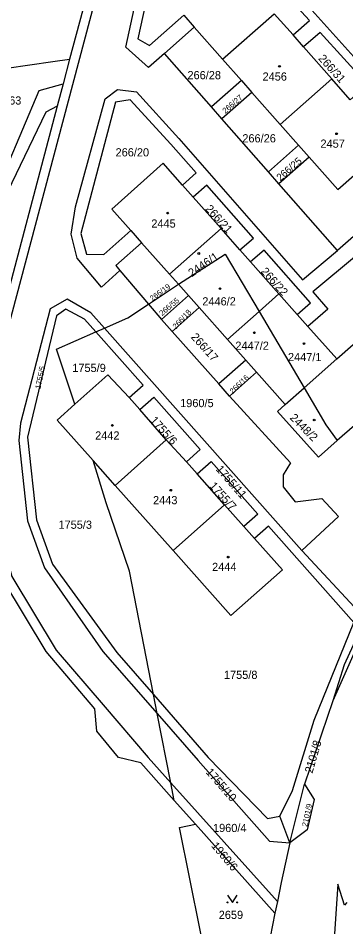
# Model space of a CAD drawing. Extents: x -679220 to -673243, y -1075091 to -1066557.
# Drawn here: x -676420.8 to -676352.8, y -1072199 to -1072010.2 of the extents above; entities that cross this region are included whole.
import ezdxf

# ---------------------------------------------------------------- set-up
doc = ezdxf.new("R2010")
doc.units = 0
for name, color, linetype in [('Hranice parcel', 7, 'Continuous'), ('Parcelní čísla', 7, 'Continuous'), ('Značky budov', 7, 'Continuous'), ('Značky kultur', 7, 'Continuous')]:
    doc.layers.add(name, color=color, linetype=linetype)

msp = doc.modelspace()

# ---------------------------------------------------------------- linework, layer by layer
at = {"layer": 'Hranice parcel'}
for p, q in [((-676405.43, -1072000.99), (-676410.13, -1072018.72)), ((-676386.44, -1072009.61), (-676384.26, -1072012.08)), ((-676378.4, -1072018.73), (-676367.67, -1072009.27)), ((-676363.77, -1072013.69), (-676367.67, -1072009.27)), ((-676384.26, -1072012.08), (-676390.45, -1072017.54)), ((-676384.26, -1072012.08), (-676378.4, -1072018.73)), ((-676361.59, -1072016.16), (-676363.77, -1072013.69)), ((-676355.71, -1072022.83), (-676361.59, -1072016.16)), ((-676410.13, -1072018.72), (-676411.49, -1072023.83)), ((-676380.72, -1072028.63), (-676390.45, -1072017.54)), ((-676378.4, -1072018.73), (-676374.5, -1072023.14)), ((-676374.5, -1072023.14), (-676380.72, -1072028.63)), ((-676374.5, -1072023.14), (-676372.32, -1072025.62)), ((-676366.44, -1072032.28), (-676355.71, -1072022.83)), ((-676351.9, -1072027.15), (-676355.71, -1072022.83)), ((-676411.49, -1072023.83), (-676412.72, -1072028.49)), ((-676372.32, -1072025.62), (-676378.54, -1072031.11)), ((-676372.32, -1072025.62), (-676366.44, -1072032.28)), ((-676412.72, -1072028.49), (-676426.83, -1072081.87)), ((-676378.54, -1072031.11), (-676380.72, -1072028.63)), ((-676368.88, -1072042.12), (-676378.54, -1072031.11)), ((-676366.44, -1072032.28), (-676362.63, -1072036.61)), ((-676362.63, -1072036.61), (-676368.88, -1072042.12)), ((-676362.63, -1072036.61), (-676360.45, -1072039.08)), ((-676360.45, -1072039.08), (-676366.74, -1072044.62)), ((-676333.89, -1072040.27), (-676354.54, -1072058.47)), ((-676366.74, -1072044.62), (-676368.88, -1072042.12)), ((-676384.52, -1072047.4), (-676386.74, -1072044.9)), ((-676354.54, -1072058.47), (-676366.74, -1072044.62)), ((-676378.69, -1072053.93), (-676384.52, -1072047.4)), ((-676397.41, -1072054.36), (-676395.19, -1072056.86)), ((-676389.38, -1072063.42), (-676378.69, -1072053.93)), ((-676374.79, -1072058.37), (-676378.69, -1072053.93)), ((-676395.19, -1072056.86), (-676389.38, -1072063.42)), ((-676372.58, -1072060.87), (-676374.79, -1072058.37)), ((-676366.7, -1072067.49), (-676372.58, -1072060.87)), ((-676399.71, -1072062.61), (-676393.75, -1072069.64)), ((-676387.53, -1072065.5), (-676389.38, -1072063.42)), ((-676393.75, -1072069.64), (-676387.53, -1072065.5)), ((-676387.53, -1072065.5), (-676385.47, -1072067.83)), ((-676354.71, -1072081.03), (-676337.16, -1072065.5)), ((-676385.47, -1072067.83), (-676391.07, -1072072.8)), ((-676383.25, -1072070.33), (-676385.47, -1072067.83)), ((-676370.83, -1072071.15), (-676366.7, -1072067.49)), ((-676362.89, -1072071.81), (-676366.7, -1072067.49)), ((-676393.75, -1072069.64), (-676391.07, -1072072.8)), ((-676388.85, -1072075.3), (-676383.25, -1072070.33)), ((-676383.25, -1072070.33), (-676377.38, -1072076.96)), ((-676377.38, -1072076.96), (-676370.83, -1072071.15)), ((-676370.83, -1072071.15), (-676361.48, -1072087.03)), ((-676360.67, -1072074.31), (-676362.89, -1072071.81)), ((-676391.07, -1072072.8), (-676388.85, -1072075.3)), ((-676404.69, -1072075.41), (-676402.91, -1072074.63)), ((-676361.93, -1072120.84), (-676402.91, -1072074.63)), ((-676379.16, -1072086.23), (-676388.85, -1072075.3)), ((-676360.67, -1072074.31), (-676354.71, -1072081.03)), ((-676377.38, -1072076.96), (-676373.56, -1072081.27)), ((-676373.56, -1072081.27), (-676379.16, -1072086.23)), ((-676373.56, -1072081.27), (-676371.34, -1072083.77)), ((-676361.48, -1072087.03), (-676354.71, -1072081.03)), ((-676371.34, -1072083.77), (-676376.94, -1072088.73)), ((-676365.39, -1072090.49), (-676371.34, -1072083.77)), ((-676376.94, -1072088.73), (-676379.16, -1072086.23)), ((-676365.39, -1072090.49), (-676361.48, -1072087.03)), ((-676397.79, -1072089.04), (-676395.56, -1072091.54)), ((-676342.98, -1072087.79), (-676354.59, -1072098)), ((-676390.07, -1072097.84), (-676395.56, -1072091.54)), ((-676400.65, -1072107.34), (-676390.07, -1072097.84)), ((-676385.89, -1072102.42), (-676390.07, -1072097.84)), ((-676400.65, -1072107.34), (-676405.26, -1072102.16)), ((-676385.89, -1072102.42), (-676383.67, -1072104.92)), ((-676377.99, -1072111.34), (-676383.67, -1072104.92)), ((-676388.66, -1072120.83), (-676400.65, -1072107.34)), ((-676388.66, -1072120.83), (-676377.99, -1072111.34)), ((-676373.97, -1072115.83), (-676377.99, -1072111.34)), ((-676373.97, -1072115.83), (-676371.74, -1072118.34)), ((-676361.93, -1072120.84), (-676350.1, -1072133.56)), ((-676391.97, -1072154.7), (-676392.74, -1072150.74)), ((-676355.54, -1072152.07), (-676361.36, -1072169.41)), ((-676389.15, -1072169.1), (-676391.97, -1072154.7)), ((-676389.15, -1072169.1), (-676367.03, -1072193.77)), ((-676388.43, -1072172.78), (-676389.15, -1072169.1)), ((-676364.45, -1072181.57), (-676361.36, -1072169.41)), ((-676384.02, -1072177.72), (-676388.43, -1072172.78)), ((-676364.45, -1072181.57), (-676366.54, -1072176.02)), ((-676384.02, -1072177.72), (-676367.53, -1072196.21)), ((-676367.03, -1072193.77), (-676367.53, -1072196.21))]:
    msp.add_line(p, q, dxfattribs=at)
for points in [[(-676295.13, -1071902.52), (-676296.41, -1071905.95), (-676304.35, -1071909.5), (-676364.66, -1071925.74), (-676375.64, -1071931.09), (-676382.94, -1071938.2), (-676387.67, -1071944.57), (-676393.17, -1071962.19), (-676409.55, -1072024.04), (-676425.12, -1072082.52), (-676427.14, -1072091.8), (-676426.89, -1072108.9), (-676422.15, -1072126.21), (-676412.96, -1072141.55), (-676403.18, -1072152.89), (-676393.86, -1072163.85), (-676389.15, -1072169.1)], [(-676390.45, -1072017.54), (-676393.75, -1072020.45), (-676398.47, -1072016.2), (-676391.69, -1071984.93), (-676388.01, -1071980.59), (-676383.5, -1071982.16), (-676332.46, -1072039.02)], [(-676375.71, -1072000.14), (-676372.54, -1071997.35), (-676384.98, -1071983.69), (-676387.9, -1071982.71), (-676389.69, -1071985.66), (-676395.95, -1072014.53), (-676393.53, -1072015.85), (-676386.44, -1072009.61)], [(-676363.77, -1072013.69), (-676360.39, -1072010.7), (-676370.32, -1071999.8), (-676373.53, -1072002.62)], [(-676234.47, -1072004.88), (-676240.04, -1072009.78), (-676249.88, -1072015.68), (-676262.29, -1072027.06), (-676264.12, -1072028.98), (-676275.42, -1072039.24), (-676288.64, -1072051.8), (-676300.61, -1072065.52), (-676311.55, -1072079.68), (-676327.13, -1072100.25), (-676343.64, -1072125.3), (-676355.54, -1072152.07)], [(-676351.9, -1072027.15), (-676348.3, -1072023.98), (-676358.17, -1072013.15), (-676361.59, -1072016.16)], [(-676434.63, -1072022.7), (-676426.51, -1072021.6), (-676423.16, -1072020.62), (-676413.61, -1072019.21), (-676410.13, -1072018.72)], [(-676432.82, -1072054.31), (-676428.64, -1072048.81), (-676425.91, -1072045.99), (-676423.22, -1072041.31), (-676416.46, -1072025.25), (-676411.49, -1072023.83)], [(-676399.71, -1072062.61), (-676403.53, -1072066.13), (-676408.6, -1072060.05), (-676409.82, -1072055.1), (-676408.9, -1072049.43), (-676402.76, -1072026.98), (-676400.17, -1072025), (-676396.28, -1072025.48), (-676387.48, -1072035.18), (-676361.81, -1072064.61), (-676354.54, -1072058.47)], [(-676412.72, -1072028.49), (-676415.04, -1072029.73), (-676423.02, -1072046.32), (-676428.56, -1072053.03), (-676432.42, -1072061.72), (-676443.33, -1072089.08)], [(-676386.74, -1072044.9), (-676383.88, -1072042.36), (-676389.14, -1072036.38), (-676397.56, -1072027.16), (-676400.58, -1072027.66), (-676407.8, -1072054.98), (-676406.6, -1072059.27), (-676403.01, -1072059.32), (-676397.41, -1072054.36)], [(-676360.45, -1072039.08), (-676354.5, -1072045.83), (-676343.77, -1072036.38), (-676349.72, -1072029.63)], [(-676386.74, -1072044.9), (-676390.69, -1072040.36), (-676401.38, -1072049.88), (-676397.41, -1072054.36)], [(-676374.79, -1072058.37), (-676371.99, -1072055.9), (-676381.67, -1072044.88), (-676384.52, -1072047.4)], [(-676334.87, -1072058.74), (-676341.13, -1072051.66), (-676359.65, -1072067.09), (-676356.54, -1072070.65), (-676360.67, -1072074.31)], [(-676395.19, -1072056.86), (-676400.56, -1072061.61), (-676399.71, -1072062.61)], [(-676362.89, -1072071.81), (-676360.15, -1072069.38), (-676369.79, -1072058.4), (-676372.58, -1072060.87)], [(-676387.53, -1072065.5), (-676377.84, -1072059.26), (-676370.83, -1072071.15)], [(-676402.91, -1072074.63), (-676405.71, -1072071.47), (-676410.64, -1072068.57), (-676414.16, -1072070.59), (-676420.3, -1072094.34), (-676420.7, -1072097.95), (-676418.87, -1072114.67), (-676415.38, -1072124.46), (-676403.22, -1072141.81), (-676391.97, -1072154.7)], [(-676402.91, -1072074.63), (-676398.02, -1072072.49), (-676393.75, -1072069.64)], [(-676404.69, -1072075.41), (-676407.03, -1072072.77), (-676410.93, -1072070.65), (-676412.84, -1072072.08), (-676418.87, -1072097.3), (-676416.99, -1072114.45), (-676413.67, -1072123.66), (-676400.33, -1072142), (-676392.74, -1072150.74)], [(-676409.08, -1072090.45), (-676412.84, -1072078.98), (-676404.69, -1072075.41)], [(-676397.79, -1072089.04), (-676394.89, -1072086.46), (-676404.69, -1072075.41)], [(-676409.08, -1072090.45), (-676402.21, -1072084.32), (-676397.79, -1072089.04)], [(-676361.48, -1072087.03), (-676356.94, -1072094.75), (-676354.59, -1072098)], [(-676388.43, -1072172.78), (-676395.38, -1072164.99), (-676399.97, -1072163.86), (-676404.47, -1072158.39), (-676404.9, -1072153.76), (-676415.03, -1072141.81), (-676423.77, -1072127.19), (-676428.78, -1072108.88), (-676429, -1072091.21), (-676428.47, -1072088.93)], [(-676395.56, -1072091.54), (-676392.67, -1072088.97), (-676383.01, -1072099.86), (-676385.89, -1072102.42)], [(-676376.94, -1072088.73), (-676364.27, -1072102.6), (-676365.85, -1072105.13), (-676365.85, -1072107.61), (-676363.32, -1072110.75), (-676357.77, -1072110.05), (-676354.36, -1072113.79), (-676361.93, -1072120.84)], [(-676405.26, -1072102.16), (-676412.75, -1072093.73), (-676409.08, -1072090.45)], [(-676354.59, -1072098), (-676358.49, -1072101.42), (-676366.98, -1072091.95), (-676365.39, -1072090.49)], [(-676392.74, -1072150.74), (-676397.74, -1072125.12), (-676402.54, -1072110.91), (-676405.26, -1072102.16)], [(-676383.67, -1072104.92), (-676380.79, -1072102.36), (-676371.1, -1072113.29), (-676373.97, -1072115.83)], [(-676351.13, -1072135.81), (-676368.88, -1072115.79), (-676371.74, -1072118.34)], [(-676371.74, -1072118.34), (-676365.94, -1072124.86), (-676376.65, -1072134.34), (-676388.66, -1072120.83)], [(-676343.37, -1072122.47), (-676350.1, -1072137.03), (-676349.75, -1072137.16), (-676353.17, -1072144.59), (-676355.54, -1072152.07)], [(-676366.54, -1072176.02), (-676363.88, -1072170.69), (-676359.39, -1072156.12), (-676351.13, -1072135.81)], [(-676392.74, -1072150.74), (-676381.37, -1072163.82), (-676369.08, -1072176.52), (-676366.54, -1072176.02)], [(-676391.97, -1072154.7), (-676383.43, -1072164.47), (-676368.67, -1072181.21), (-676364.45, -1072181.57)], [(-676361.36, -1072169.41), (-676359.42, -1072172.6), (-676360.84, -1072178.87), (-676364.45, -1072181.57)], [(-676380.93, -1072210.38), (-676387.33, -1072178.39), (-676384.02, -1072177.72)], [(-676364.45, -1072181.57), (-676366.23, -1072189.82), (-676367.03, -1072193.77)], [(-676352.6, -1072193.99), (-676353.07, -1072194.56), (-676354.48, -1072190.21), (-676356.32, -1072217.97), (-676356.26, -1072225.84), (-676355.73, -1072232.24), (-676354.59, -1072242.56), (-676354.54, -1072246.62)], [(-676367.53, -1072196.21), (-676368.55, -1072201.2), (-676369.91, -1072205.35)]]:
    msp.add_lwpolyline(points, dxfattribs=at)
at = {"layer": 'Značky budov'}
for centre in [(-676366.58, -1072020.2), (-676354.74, -1072034.23), (-676389.78, -1072050.72), (-676383.33, -1072059.11), (-676378.94, -1072066.41), (-676371.8, -1072075.58), (-676361.49, -1072077.83), (-676401.26, -1072094.85), (-676359.38, -1072093.72), (-676389.15, -1072108.3), (-676377.22, -1072122.2)]:
    msp.add_circle(centre, 0.175, dxfattribs=at)
at = {"layer": 'Značky kultur'}
msp.add_lwpolyline([(-676377.35, -1072192.47), (-676376.35, -1072193.97), (-676375.35, -1072192.47)], dxfattribs=at)
for centre in [(-676377.35, -1072193.97), (-676375.35, -1072193.97)]:
    msp.add_circle(centre, 0.1, dxfattribs=at)

# ---------------------------------------------------------------- texts
at = {"layer": 'Parcelní čísla'}
for s, height, rotation, p in [('266/31', 1.7, 312, (-676358.63, -1072018.67)), ('266/27', 1.2, 41, (-676377.81, -1072030.12)), ('266/25', 1.5, 41, (-676366.42, -1072044.14)), ('266/21', 1.7, 312, (-676382.1, -1072049.91)), ('2446/1', 1.7, 34, (-676384.8, -1072064.05)), ('266/22', 1.7, 312, (-676370.57, -1072062.93)), ('266/19', 1.14, 36, (-676392.99, -1072069.06)), ('266/55', 1.14, 40, (-676390.96, -1072072.15)), ('266/18', 1.14, 47, (-676388.07, -1072074.9)), ('266/17', 1.7, 312, (-676385.07, -1072076.56)), ('1755/5', 1.14, 78, (-676416.2, -1072087.34)), ('266/16', 1.14, 44, (-676376.28, -1072088.38)), ('2448/2', 1.7, 315, (-676364.57, -1072093.38)), ('1755/6', 1.7, 312, (-676393.55, -1072093.89)), ('1755/11', 1.7, 311, (-676379.89, -1072104.02)), ('1755/7', 1.7, 312, (-676381.25, -1072107.51)), ('2101/8', 1.7, 74, (-676359.76, -1072167.24)), ('1755/10', 1.7, 311, (-676381.98, -1072166.97)), ('2101/9', 1.14, 78, (-676360.83, -1072178.3)), ('1960/6', 1.7, 310, (-676380.84, -1072182.27))]:
    msp.add_text(s, height=height, rotation=rotation, dxfattribs=at).set_placement(p)
for s, p in [('266/28', (-676385.68, -1072022.89)), ('2456', (-676370.1, -1072023.18)), ('263', (-676423.95, -1072028.16)), ('266/26', (-676374.29, -1072036.02)), ('2457', (-676358.08, -1072037.13)), ('266/20', (-676400.6, -1072038.93)), ('2445', (-676393.18, -1072053.73)), ('2446/2', (-676382.6, -1072069.9)), ('2447/2', (-676375.74, -1072079.12)), ('2447/1', (-676364.82, -1072081.48)), ('1755/9', (-676409.58, -1072083.73)), ('1960/5', (-676387.2, -1072091.04)), ('2442', (-676404.84, -1072097.78)), ('2443', (-676392.82, -1072111.22)), ('1755/3', (-676412.45, -1072116.32)), ('2444', (-676380.57, -1072125.09)), ('1755/8', (-676378.11, -1072147.52)), ('1960/4', (-676380.38, -1072179.34)), ('2659', (-676379.19, -1072197.4))]:
    msp.add_text(s, height=1.7, dxfattribs=at).set_placement(p)

doc.saveas('drawing.dxf')
